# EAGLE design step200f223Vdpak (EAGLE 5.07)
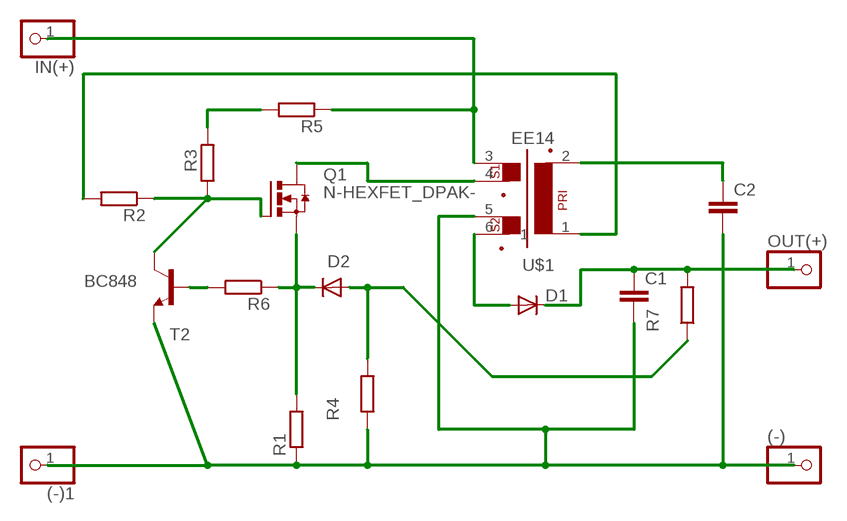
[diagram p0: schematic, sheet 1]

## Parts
(-)  PINHD-1X11MM6  [1X1MM8]
(-)1  PINHD-1X11MM6  [1X1MM8]
C1  C-EU025-025X050  [C025-025X050]
C2  C-EUC0805  [C0805]
D1  DIODE-SMA-DO214  [SMA-DO214AC]
D2  DIODE-MINIMELF  [MINIMELF]
IN(+)  PINHD-1X11MM6  [1X1MM8]
OUT(+)  PINHD-1X11MM6  [1X1MM8]
Q1  N-HEXFET_DPAK-  [TO252]
R1  R-EU_R1206  [R1206]
R2  R-EU_R0805  [R0805]
R3  R-EU_R1206  [R1206]
R4  R-EU_R1206  [R1206]
R5  R-EU_R1206  [R1206]
R6  R-EU_R0805  [R0805]
R7  R-EU_R1206  [R1206]
T2  BC848  [SOT23]
U$1  EE14  [EE14]

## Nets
A: D1.A U$1.6
B1C2: Q1.1(G) R2.1 R3.1 T2.C
C1: Q1.3(D) U$1.4
EB: D2.C Q1.2(S) R1.2 R6.1
N$1: R3.2 R5.2
N$2: R6.2 T2.B
N$3: D2.A R4.2 R7.1
N$4: R2.2 U$1.1
N$6: C2.1 U$1.2
V+: IN(+).1 R5.1 U$1.3
V-: (-)1.1 (-).1 C1.2 C2.2 R1.1 R4.1 T2.E U$1.5
VOUT+: C1.1 D1.K(C) OUT(+).1 R7.2

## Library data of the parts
(-) (-)1 IN(+) OUT(+) = pinhead:PINHD-1X1: PIN HEADER
C1 C2 = rcl:C-EU: CAPACITOR, European symbol
D1 D2 = diode:DIODE-: DIODE
Q1 = transistor-power:N-HEXFET_?-*: HEXFET® Power MOSFET
R1-R7 = rcl:R-EU_: RESISTOR, European symbol
T2 = transistor:BC848: NPN TRANSISTOR
U$1 = trafo:EE14

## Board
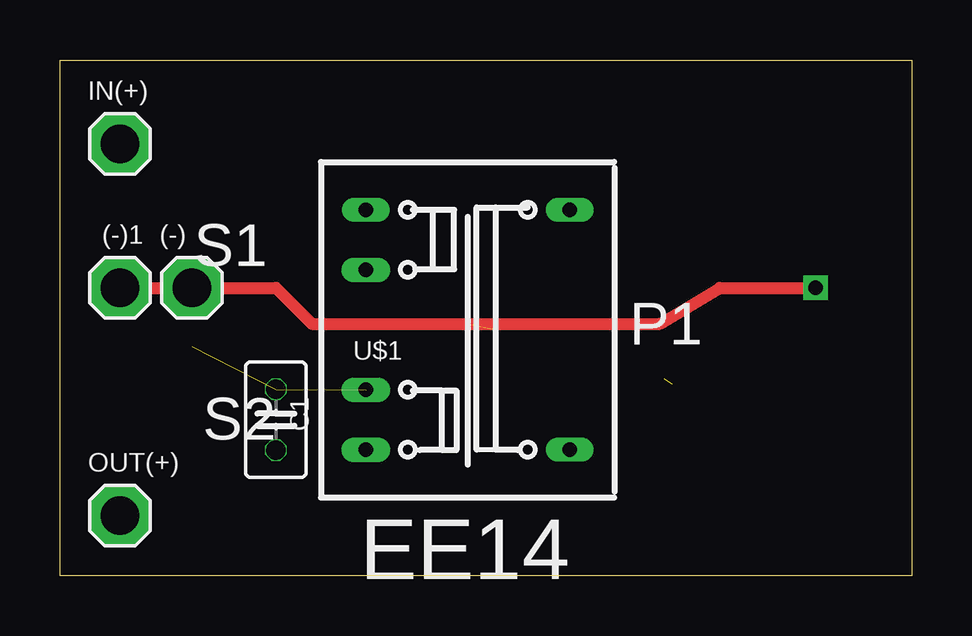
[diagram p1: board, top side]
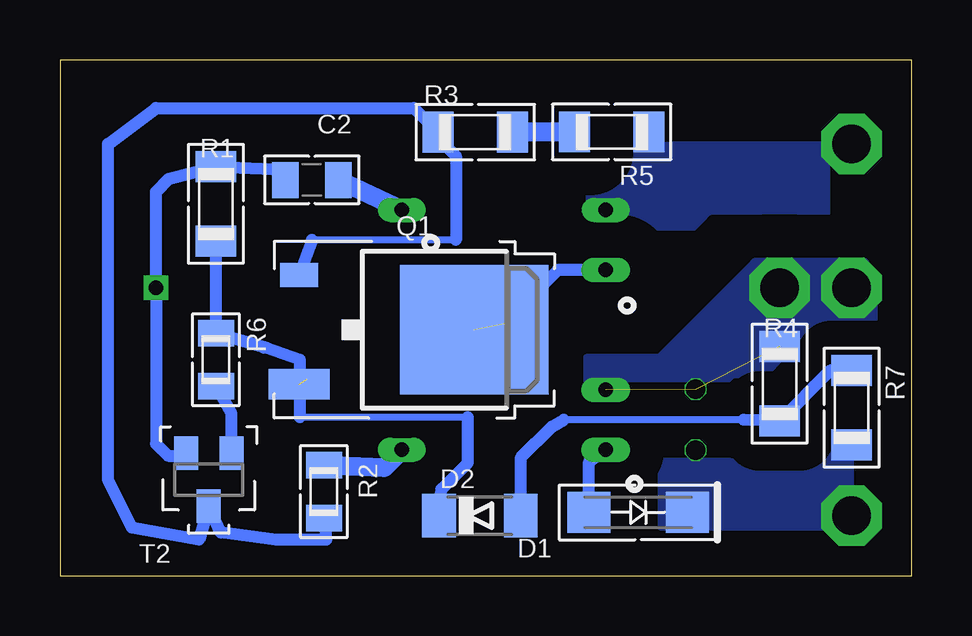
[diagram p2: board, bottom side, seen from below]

Size 35.5 x 21.5 mm. Coordinates in mm from the lower left corner, seen from the top.
Outline: 0,21.5 35.5,21.5 35.5,0 0,0 0,21.5
Copper layers (1*16): Top 0.035mm / dielectric 1.5mm / Bottom 0.035mm
Design rules "default": minimum track width 10mil, minimum drill 20mil, track to track 8mil, track to pad 8mil, pad to pad 8mil, via to via 8mil, smd to smd 8mil, copper to edge 40mil, drill to drill 8mil, minimum pad ring 1mil, minimum via ring 8mil, stop-mask expansion 4mil, vias tented up to drill 0mil, thermal gap 10mil

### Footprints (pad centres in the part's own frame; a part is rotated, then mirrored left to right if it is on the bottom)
1X1MM8 = drill 1.6 pad 2.54 octagon: 1 0,0
C025-025X050 = drill 0.813 octagon: 1 -1.27,0; 2 1.27,0
C0805 = smd 1.1 x 1.5: 1 -1.1,0; 2 1.1,0
SMA-DO214AC = smd 1.8 x 1.7: A 2.05,-0.127; K -2.05,-0.127
MINIMELF = smd 1.4 x 1.8: A 1.7,0; C -1.7,0
TO252 = smd 1 x 1.6: 1 -2.28,-3.53 | smd 1.27 x 2.54: 2 2.28,-3.53 | smd 5.4 x 6.2: 3 0,3.77
R1206 = smd 1.3 x 1.7: 1 -1.55,0; 2 1.55,0
R0805 = smd 1.1 x 1.5: 1 -1.1,0; 2 1.1,0
SOT23 = smd 1 x 1.4: B -0.95,-1.1; C 0,1.1; E 0.95,-1.1
EE14 = drill 0.6 pad 1 long: 1 4.25,-5; 2 4.25,5; 3 -4.25,5 | drill 0.6 pad 1.016 long: 4 -4.25,2.5; 5 -4.25,-2.5; 6 -4.25,-5

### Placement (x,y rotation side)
(-)  5.5,12 0 top
(-)1  2.5,12 0 top
C1  9,6.5 90 top
C2  25,16.5 180 bottom
D1  11.39,2.51 180 bottom
D2  18,2.5 0 bottom
IN(+)  2.5,18 0 top
OUT(+)  2.5,2.5 0 top
Q1  22,10.25 270 bottom
R1  29,15.5 270 bottom
R2  24.5,3.5 90 bottom
R3  18.19,18.49 0 bottom
R4  5.5,8 270 bottom
R5  12.5,18.5 180 bottom
R6  29,9 270 bottom
R7  2.5,7 270 bottom
T2  29.3,4 180 bottom
U$1  17,10.25 0 top

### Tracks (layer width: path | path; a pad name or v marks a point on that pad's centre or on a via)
A
  Bottom 0.5: U$1.6 13.45,4.75 D1.A
B1C2
  Bottom 0.3: 19,14 25,14
  Bottom 0.5: R2.1 24.4,1.5 26.5,1.5 28.8,1.8 T2.C 29.7,1.5 32.5,2 33.5,4 33.5,18 31.5,19.5 20.75,19.5 R3.1 19.74,18.24 19,17.5 19,14 | 25,14 Q1.1
C1  (1 unrouted)
  Bottom 0.5: U$1.4 14.75,12.75 17,10.5
EB  (1 unrouted)
  Bottom 0.3: 18.5,6.6 25.5,6.6
  Bottom 0.5: R1.2 R6.1 26.9,9.5 | 25.19,8.19 25.5,8.5 25.5,9 26.9,9.5 | 26.9,9.5 27,9.5 | D2.C 19.6,3.6 18.5,4.7 18.5,6.6 | 25.5,6.6 25.5,7.94 Q1.2
N$1
  Bottom 0.8: R5.2 15.63,18.5 R3.2
N$2
  Bottom 0.5: T2.B 28.35,6.75 R6.2
N$3
  Bottom 0.3: 7,6.5 14.5,6.5
  Bottom 0.5: D2.A 16.3,4.9 15,6.2 14.5,6.5 | 7,6.5 R4.2 3.4,8.55 R7.1
N$4
  Bottom 0.8: R2.2 22,4.5 U$1.1
N$6
  Bottom 0.8: U$1.2 C2.1
V+
  pour Bottom (isolate 1.8, rank 4, no thermals): 3.5,18 10,18 12.1,17.9 13.1,17.4 13.5,17 13.5,14.5 3.5,14.5
V-  (via drill 0.6)  (2 unrouted)
  Top 0.5: (-)1.1 9,12 10.5,10.5 25,10.5 27.5,12 v31.5,12
  Bottom 0.5: T2.E 30.35,5 31,5 31.5,5.5 v31.5,12 31.5,16 30.95,16.55 R1.1 26.6,16.95 C2.2
  pour Bottom (isolate 1.422, no thermals): 2,13 6.5,13 10.5,9 13.5,9 13.5,7 9,7 7.5,8.5 3.5,8.5 1.5,10.5
VOUT+
  pour Bottom (isolate 1.422, rank 3, no thermals): 2.5,5.5 10,5.5 10.5,5 10.5,2 2.5,2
